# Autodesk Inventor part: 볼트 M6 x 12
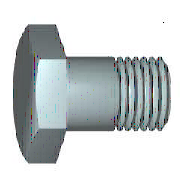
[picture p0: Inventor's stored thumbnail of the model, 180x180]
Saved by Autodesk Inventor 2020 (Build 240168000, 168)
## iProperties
Created: 2012-02
Part Number: 볼트 M6 x 12
Material: 스테인리스강
Description: 6각 머리 나사. 제품 등급 C
Document SubType Name: Modeling
Standard: ISO 4018
Designer: mduedu
Standard Revision: Third edition 1999-08-15
Standards Organization: ISO
Language: ko-KR
Size Designation: M6 x 12
Categories: <MemberInstance><Categories><Category DisplayName="조임쇠" InternalName="e4da775c-781d-43d5-af7c-5136215cf5a6" Mnemonic="FSTN"><Category DisplayName="볼트" InternalN
Density: 8.08 g/cm^3
Appearance: 반광택
IsCustomPart: 0
Author: mduedu
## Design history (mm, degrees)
node "WorkPlane1"
node "WorkPoint1"
node "MSC_A1"
node "MSC_PF1"
node "MSC_PT1"
body "Solid1"
node "스케치1"
sketch "스케치2"
  geometry: L1 (-5, 2.887)-(-5, -2.887); L2 (0, 5.773)-(-5, 2.887); L3 (5, 2.887)-(0, 5.773); L4 (5, -2.887)-(5, 2.887); L5 (0, -5.773)-(5, -2.887); L6 (-5, -2.887)-(0, -5.773); C1 r 5 at (0, 0); 1 further point
  constraints: 12 end point, 6 tangent, 2 parallel, 2 vertical, 1 centre point
  dimensions: "d1" = 10 diameter of C1 (= ParS); "d29" = 0 distance of point (0, 0) C1.centre; "d30" = 0 distance of C1.centre point (0, 0)
extrude "돌출1" new body sketch "스케치2" distance "d6" = 4 (= ParK); taper "d7" = 0 deg
revolve "회전1" stored, may be unused: angle "d14" = 360 deg
revolve "회전2" stored, may be unused: angle "d21" = 360 deg
chamfer "모따기1" distance "d22" = 0.5 (= 0.5 x PTC); stored, may be unused: second distance "d23" = 0.5 (= 0.5 x PTC), angle "d39" = 45 deg
fillet "모깎기1" dims "d24" = 0.25 (= r)
feature "스레드1" dims "d32" = 0, "b" = 10.5 (= NLG - 1.5 x PTC)
sketch "스케치3"
  geometry: L1 (5, 4)-(5.873, 4); L2 (5.873, 3.496)-(5, 4); L3 (5.873, 4)-(5.873, 3.496); L4 (0, -0.8)-(0, 4.8) reference; L5 (5.773, 0)-(5.773, 4) reference
  constraints: 6 end point, 1 horizontal, 1 vertical
  dimensions: "d25" = 0.1 distance between parallel lines of L5 L3; "d26" = 0 distance from line of L5.end L1; "d27" = 60 deg angle of L3 L2; "d28" = 5 distance from line of L4 L1.start (= 0.5 x ParS)
sketch "스케치4"
  geometry: L1 (0, -12)-(0, 0); L2 (-3, -12)-(0, -12); L3 (-3, 0)-(-3, -12); L4 (0, 0)-(-3, 0); L5 (0, -12)-(0, 0); L6 (-3.6, 0)-(0.6, 0) reference; L7 (0, -14.4)-(0, 2.4) reference
  constraints: 10 end point, 2 horizontal, 2 vertical
  dimensions: "d18" = 3 distance of L1.start L2.start (= 0.5 x NND); "d20" = 12 distance of L3.start L2.start (= NLG); "d33" = 0 distance between parallel lines of L7 L1; "d34" = 0 distance between parallel lines of L6 L4
other parameters: "NND" = 6 [user parameter; used in 2 equation terms], "NLG" = 12 [user parameter; used in 2 equation terms], "PTC" = 1 [user parameter; used in 3 equation terms], "ParK" = 4 [user parameter; used in 1 equation term], "ParS" = 10 [user parameter; used in 3 equation terms], "msp_es" = 5.77367 (= 0.577367 x ParS) [user parameter], "r" = 0.25 [user parameter; used in 1 equation term], "d2" = 15 (derived), "d4" = 17.32102 (derived), "d8" = 15 (derived), "d10" = 0 (derived), "d12" = 30 deg (derived), "d15" = 0 (derived), "d37" = 0, "d38" = 0, "d40" = 0, "d41" = 0, "d42" = 0, "THREADDIA" = 6 (= NND) [user parameter]
